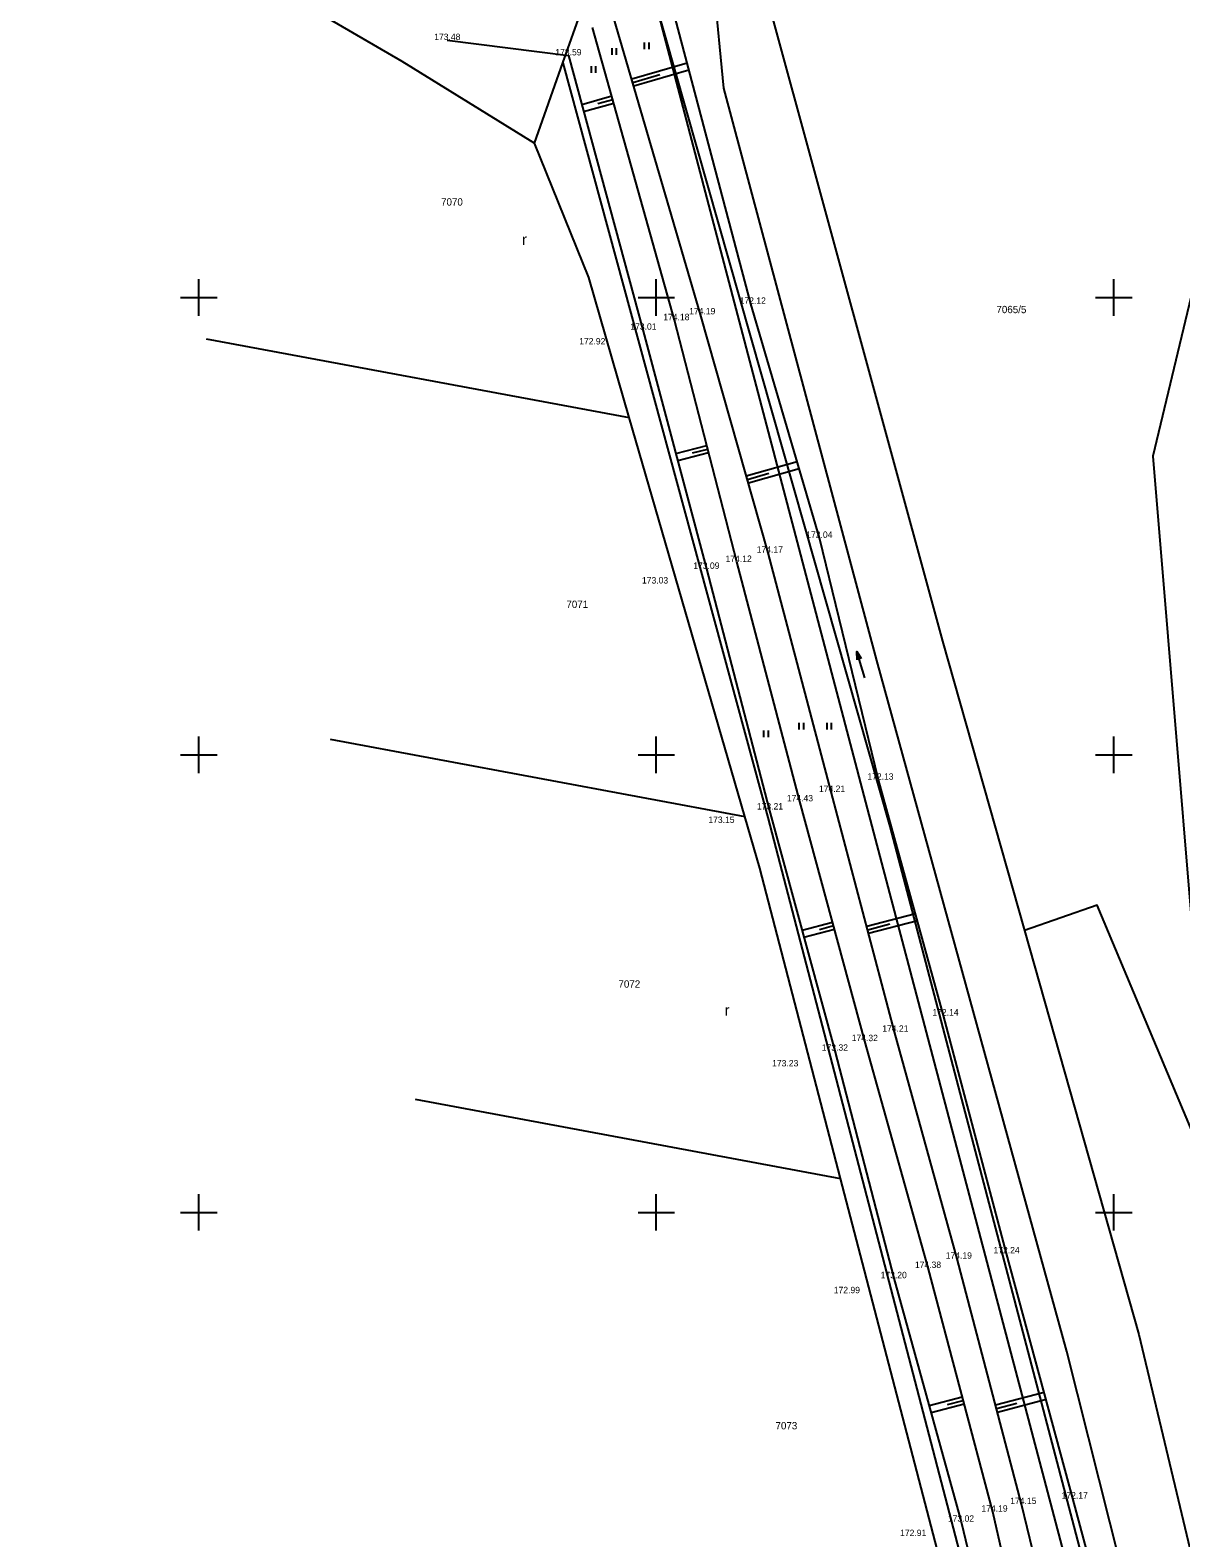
# Model space of a CAD drawing. Extents: x -612546 to -611926, y -1201932 to -1200444.
# Drawn here: x -612118.5 to -611992.7, y -1201435.6 to -1201270.8 of the extents above; entities that cross this region are included whole.
import ezdxf

# ---------------------------------------------------------------- set-up
doc = ezdxf.new("R2010")
doc.units = 0
for name, color, linetype in [('14 hrana pata svahu', 7, 'Continuous'), ('15 šrafy', 7, 'Continuous'), ('61 legenda křížky', 7, 'Continuous'), ('Hranice parcel', 7, 'Continuous'), ('Parcelní čísla', 7, 'Continuous'), ('Vnitřní kresba', 7, 'Continuous'), ('Vrstva 36', 7, 'Continuous'), ('Vrstva 45', 7, 'Continuous'), ('výška bodu', 7, 'Continuous')]:
    doc.layers.add(name, color=color, linetype=linetype)

msp = doc.modelspace()

# ---------------------------------------------------------------- linework, layer by layer
at = {"layer": '14 hrana pata svahu'}
for points in [[(-612064.14, -1201607.91), (-612050.9, -1201587.38), (-612035.24, -1201565.59), (-612018.94, -1201543.69), (-612007.37, -1201523.79), (-612001.85, -1201507.73), (-611999.98, -1201490.48), (-612000.59, -1201475.99), (-612003.88, -1201457.4), (-612010.08, -1201431.88), (-612017.13, -1201405.07), (-612023.96, -1201380.26), (-612030.88, -1201354.05), (-612037.79, -1201327.9), (-612045.18, -1201301.85), (-612055.08, -1201267.97)], [(-612058.46, -1201609.91), (-612045.84, -1201591.45), (-612030, -1201569.15), (-612014.09, -1201547.19), (-612002.14, -1201525.81), (-611996.32, -1201508.86), (-611994.18, -1201490.81), (-611994.04, -1201475.36), (-611997.78, -1201456.26), (-612004.46, -1201431.28), (-612011.71, -1201404.48), (-612018.59, -1201378.49), (-612025.7, -1201352.72), (-612032.15, -1201326.28), (-612039.66, -1201300.7), (-612048.13, -1201268.75)], [(-612067.33, -1201605.71), (-612054.19, -1201585.24), (-612037.82, -1201563.34), (-612021.49, -1201542.15), (-612010.23, -1201522.18), (-612005.1, -1201506.94), (-612003.52, -1201490.49), (-612004.34, -1201476.58), (-612007.48, -1201457.96), (-612013.23, -1201432.72), (-612020.3, -1201406.08), (-612027.21, -1201381.29), (-612034.3, -1201355.08), (-612041.2, -1201328.91), (-612048.01, -1201302.49), (-612056.96, -1201270.5)], [(-612072.85, -1201271.87), (-612059.61, -1201273.55), (-612051.46, -1201303.54), (-612044.5, -1201329.67), (-612037.67, -1201355.97), (-612030.48, -1201382.34), (-612024.02, -1201407.2), (-612016.67, -1201433.81), (-612010.74, -1201458.51), (-612007.4, -1201477.04), (-612007.3, -1201490.69), (-612008.02, -1201506.4), (-612013.93, -1201520.48), (-612024.51, -1201540.1), (-612040.53, -1201561.53), (-612057.63, -1201582.88), (-612071.39, -1201603.6)]]:
    msp.add_lwpolyline(points, dxfattribs=at)
at = {"layer": '15 šrafy'}
for p, q in [((-612046.64, -1201274.38), (-612052.69, -1201276.15)), ((-612049.62, -1201275.67), (-612052.58, -1201276.53)), ((-612046.43, -1201275.15), (-612052.47, -1201276.92)), ((-612058.16, -1201278.9), (-612054.87, -1201277.98)), ((-612057.95, -1201279.67), (-612054.65, -1201278.75)), ((-612056.4, -1201278.82), (-612054.76, -1201278.36)), ((-612047.86, -1201317.05), (-612044.48, -1201316.18)), ((-612047.65, -1201317.83), (-612044.28, -1201316.96)), ((-612046.03, -1201316.99), (-612044.38, -1201316.57)), ((-612034.59, -1201317.96), (-612040.16, -1201319.54)), ((-612037.69, -1201319.25), (-612040.05, -1201319.92)), ((-612034.37, -1201318.73), (-612039.94, -1201320.31)), ((-612034.07, -1201369.17), (-612030.73, -1201368.27)), ((-612032.17, -1201369.07), (-612030.63, -1201368.65)), ((-612021.66, -1201367.36), (-612027, -1201368.76)), ((-612024.47, -1201368.51), (-612026.89, -1201369.15)), ((-612021.45, -1201368.13), (-612026.79, -1201369.54)), ((-612033.86, -1201369.94), (-612030.52, -1201369.04)), ((-612007.6, -1201419.68), (-612012.92, -1201421.08)), ((-612020.18, -1201421.12), (-612016.56, -1201420.16)), ((-612019.96, -1201421.89), (-612016.36, -1201420.93)), ((-612018.16, -1201421), (-612016.46, -1201420.55)), ((-612010.6, -1201420.89), (-612012.82, -1201421.47)), ((-612007.39, -1201420.46), (-612012.72, -1201421.86))]:
    msp.add_line(p, q, dxfattribs=at)
at = {"layer": '61 legenda křížky'}
for p, q in [((-612100, -1201302), (-612100, -1201298)), ((-612050, -1201302), (-612050, -1201298)), ((-612000, -1201302), (-612000, -1201298)), ((-612102, -1201300), (-612098, -1201300)), ((-612052, -1201300), (-612048, -1201300)), ((-612002, -1201300), (-611998, -1201300)), ((-612100, -1201352), (-612100, -1201348)), ((-612050, -1201352), (-612050, -1201348)), ((-612000, -1201352), (-612000, -1201348)), ((-612102, -1201350), (-612098, -1201350)), ((-612052, -1201350), (-612048, -1201350)), ((-612002, -1201350), (-611998, -1201350)), ((-612100, -1201402), (-612100, -1201398)), ((-612050, -1201402), (-612050, -1201398)), ((-612000, -1201402), (-612000, -1201398)), ((-612102, -1201400), (-612098, -1201400)), ((-612052, -1201400), (-612048, -1201400)), ((-612002, -1201400), (-611998, -1201400))]:
    msp.add_line(p, q, dxfattribs=at)
at = {"layer": 'Hranice parcel'}
for p, q in [((-612063.31, -1201283.15), (-612060.22, -1201274.37)), ((-612099.22, -1201304.53), (-612052.95, -1201313.13)), ((-612040.32, -1201356.72), (-612052.95, -1201313.13)), ((-612015.54, -1201451.28), (-612029.85, -1201396.29))]:
    msp.add_line(p, q, dxfattribs=at)
for points in [[(-612115.48, -1201252.1), (-612115.07, -1201252.28), (-612095.11, -1201264.08), (-612077.83, -1201274.18), (-612063.31, -1201283.15)], [(-612060.22, -1201274.37), (-612058.16, -1201268.54), (-612056.92, -1201265.29), (-612055.38, -1201261.27), (-612054.58, -1201259.18), (-612053.61, -1201256.64)], [(-612038.38, -1201265.42), (-612018.73, -1201337.57), (-612009.76, -1201369.19)], [(-612177.46, -1201854.09), (-612171.97, -1201847.65), (-612125.97, -1201786.38), (-612109.19, -1201764.04), (-612092.57, -1201737.14), (-612080.39, -1201714.9), (-612074.78, -1201703.41), (-612071.98, -1201691.65), (-612072.2, -1201658.35), (-612070, -1201637.27), (-612065.73, -1201619.85), (-612059.82, -1201607.37), (-612039.46, -1201577.1), (-612017, -1201547.24), (-612004.68, -1201526.81), (-611998.92, -1201511.99), (-611996.24, -1201493.62), (-611996.58, -1201479.8), (-612000.74, -1201455.02), (-612027.1, -1201355.18), (-612050.25, -1201267.11)], [(-611983.63, -1201266.82), (-611995.73, -1201317.36), (-611989.14, -1201396.64)], [(-612060.22, -1201274.37), (-612037.81, -1201356.84), (-612011.62, -1201457.28), (-612007.48, -1201483.41), (-612008.37, -1201502.54), (-612012.46, -1201517.21), (-612025.5, -1201540.7), (-612047.75, -1201570.04), (-612070.24, -1201601.65), (-612078.31, -1201621), (-612081.97, -1201637.65), (-612083.96, -1201662.29), (-612084.12, -1201685.12), (-612084.75, -1201695.31), (-612087.47, -1201703.35), (-612103.05, -1201731.95), (-612118.98, -1201757.79), (-612136.57, -1201780.34), (-612179.16, -1201837.25), (-612189.22, -1201833.81)], [(-612052.95, -1201313.13), (-612057.38, -1201297.82), (-612063.31, -1201283.15)], [(-612085.65, -1201348.29), (-612040.32, -1201356.72)], [(-612029.85, -1201396.29), (-612038.68, -1201362.39), (-612040.32, -1201356.72)], [(-611989.14, -1201396.64), (-612001.79, -1201366.41), (-612009.76, -1201369.19)], [(-612009.76, -1201369.19), (-611997.24, -1201413.36), (-611984.77, -1201465.78), (-611983.62, -1201488.16), (-611987.79, -1201519.18), (-611996.06, -1201535.15)], [(-612076.37, -1201387.64), (-612029.85, -1201396.29)]]:
    msp.add_lwpolyline(points, dxfattribs=at)
at = {"layer": 'Vnitřní kresba'}
for points in [[(-612167.45, -1201850.95), (-612159.31, -1201839.87), (-612135.2, -1201807.83), (-612099.97, -1201758.55), (-612082.71, -1201730.21), (-612068.43, -1201702.85), (-612066.16, -1201687.46), (-612066.16, -1201656.85), (-612064.63, -1201639.3), (-612057.32, -1201615.06), (-612036.83, -1201583.77), (-612007.13, -1201540.95), (-611995.21, -1201517.05), (-611990.85, -1201487.68), (-611992.18, -1201466.53), (-612005.11, -1201415.22), (-612025.88, -1201339.7), (-612042.61, -1201277.13), (-612043.67, -1201266.17)], [(-612170.38, -1201848.81), (-612152.03, -1201823.55), (-612114.84, -1201773.75), (-612096.57, -1201746.92), (-612078.95, -1201716.04), (-612070.37, -1201697.01), (-612068.25, -1201638.15), (-612062.56, -1201619.7), (-612053.03, -1201601.55), (-612018.56, -1201552.89), (-611999.85, -1201519.56), (-611995.35, -1201499.82), (-611993.63, -1201480.57), (-612000.19, -1201450.02), (-612024.45, -1201357.81), (-612050.25, -1201267.11)]]:
    msp.add_lwpolyline(points, dxfattribs=at)
at = {"layer": 'Vrstva 36'}
for p, q in [((-612054.84, -1201273.49), (-612054.84, -1201272.74)), ((-612054.34, -1201273.49), (-612054.34, -1201272.74)), ((-612051.29, -1201272.87), (-612051.29, -1201272.12)), ((-612050.79, -1201272.87), (-612050.79, -1201272.12)), ((-612057.1, -1201275.46), (-612057.1, -1201274.71)), ((-612056.6, -1201275.46), (-612056.6, -1201274.71)), ((-612038.24, -1201348.08), (-612038.24, -1201347.33)), ((-612037.74, -1201348.08), (-612037.74, -1201347.33)), ((-612034.37, -1201347.24), (-612034.37, -1201346.49)), ((-612033.87, -1201347.24), (-612033.87, -1201346.49)), ((-612031.34, -1201347.24), (-612031.34, -1201346.49)), ((-612030.84, -1201347.24), (-612030.84, -1201346.49))]:
    msp.add_line(p, q, dxfattribs=at)
at = {"layer": 'Vrstva 45'}
msp.add_line((-612027.21, -1201341.57), (-612028.07, -1201338.69), dxfattribs=at)
msp.add_lwpolyline([(-612028.04, -1201339.6), (-612028.07, -1201338.69), (-612027.6, -1201339.47)], dxfattribs=at)

# ---------------------------------------------------------------- texts
at = {"layer": 'Parcelní čísla'}
for s, p in [('7070', (-612073.53, -1201289.96)), ('7065/5', (-612012.82, -1201301.72)), ('7071', (-612059.83, -1201333.94)), ('7072', (-612054.14, -1201375.44)), ('7073', (-612036.97, -1201423.72))]:
    msp.add_text(s, height=0.8, dxfattribs=at).set_placement(p)
at = {"layer": 'Vrstva 36'}
for p in [(-612064.69, -1201294.27), (-612042.53, -1201378.51)]:
    msp.add_text('r', height=1.2, dxfattribs=at).set_placement(p)
at = {"layer": 'výška bodu'}
for s, p in [('173.48', (-612074.28, -1201271.87)), ('173.59', (-612061.04, -1201273.55)), ('174.19', (-612046.41, -1201301.85)), ('172.12', (-612040.89, -1201300.7)), ('173.01', (-612052.84, -1201303.54)), ('174.18', (-612049.24, -1201302.49)), ('172.92', (-612058.43, -1201305.14)), ('172.04', (-612033.61, -1201326.28)), ('174.17', (-612039.02, -1201327.9)), ('173.09', (-612045.96, -1201329.67)), ('174.12', (-612042.43, -1201328.91)), ('173.03', (-612051.57, -1201331.27)), ('172.13', (-612026.93, -1201352.72)), ('174.21', (-612032.22, -1201354.05)), ('173.21', (-612039.01, -1201355.97)), ('174.43', (-612035.73, -1201355.08)), ('173.15', (-612044.31, -1201357.44)), ('172.14', (-612019.82, -1201378.49)), ('174.21', (-612025.3, -1201380.26)), ('173.32', (-612031.91, -1201382.34)), ('174.32', (-612028.64, -1201381.29)), ('173.23', (-612037.34, -1201384.05)), ('174.19', (-612018.36, -1201405.07)), ('172.24', (-612013.14, -1201404.48)), ('173.20', (-612025.48, -1201407.2)), ('174.38', (-612021.73, -1201406.08)), ('172.99', (-612030.6, -1201408.84)), ('174.15', (-612011.31, -1201431.88)), ('172.17', (-612005.69, -1201431.28)), ('173.02', (-612018.13, -1201433.81)), ('174.19', (-612014.46, -1201432.72)), ('172.91', (-612023.35, -1201435.38))]:
    msp.add_text(s, height=0.7, dxfattribs=at).set_placement(p)

doc.saveas('drawing.dxf')
